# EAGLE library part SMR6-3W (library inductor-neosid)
TRANSFORMER SMD toroidal-core transformer with 3 windings
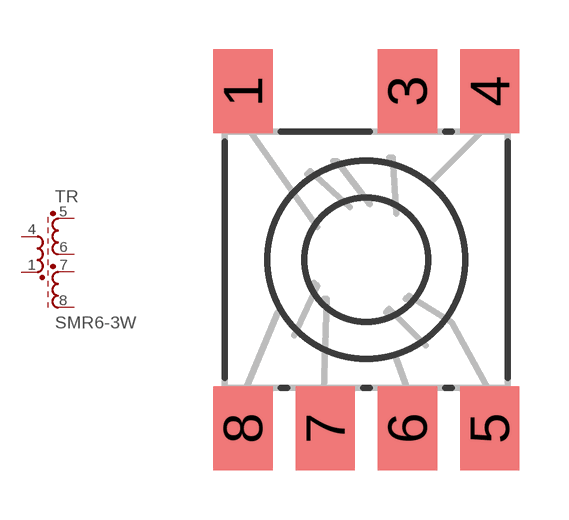
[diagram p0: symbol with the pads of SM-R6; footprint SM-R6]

Designator prefix TR

## SMR6-3W (OC_FARNELL: unknown; OC_NEWARK: unknown)  [SM-R6]
1  1  pas
4  4  pas
5  5  pas
6  6  pas
7  7  pas
8  8  pas

## Footprint SM-R6 (pad centres in mm)
SMD TOROIDAL CORE TRANSFORMER 10.8 x 8.8 x 5.5 mm
smd 1.8 x 2.55: 1 -3.75,5.125; 3 1.25,5.125; 4 3.75,5.125; 5 3.75,-5.125; 6 1.25,-5.125; 7 -1.25,-5.125; 8 -3.75,-5.125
